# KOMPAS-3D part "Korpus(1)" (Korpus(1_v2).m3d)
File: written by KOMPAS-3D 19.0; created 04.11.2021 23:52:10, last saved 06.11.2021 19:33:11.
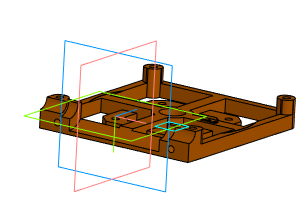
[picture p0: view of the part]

Document properties: Полное имя файла: D:\3D_print\3D проекты Компас 3D\Редуктор (Снова)\Korpus(1_v2).m3d

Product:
- Part/product: Korpus(1)
    Материал: АБС 0603Т ТУ 2214-019-002 03521-96 (density 0 kg/m3)

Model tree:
1. Смещенная плоскость:1  (labels: Подшипник 23 ГОСТ 8338-75\Наружное кольцо; Korpus(1); Операция вращения:1; Операция вращения:1)
     Расстояние = 1.6
2. Эскиз:2  (labels: Подшипник 23 ГОСТ 8338-75\Наружное кольцо; Korpus(1); Скругление:2; Скругление:2)
3. Элемент выдавливания:1  (labels: Korpus(1))
     Расстояние 1 = 11.5
4. Эскиз:3  (labels: Korpus(1))
5. Элемент выдавливания:2
     Расстояние 1 = 34.6; Расстояние 2 = 34.6
6. Эскиз:4  (labels: Korpus(1))
7. Элемент выдавливания:3  (labels: Подшипник 23 ГОСТ 8338-75\Наружное кольцо; Korpus(1); Операция вращения:1; Операция вращения:1)
     Расстояние 1 = 25.2; Смещение 1 = 0.3; Расстояние 2 = 25.2; Смещение 2 = 0.3
8. Эскиз:6  (with: Эскиз:1)  (labels: Korpus(1))
9. Элемент выдавливания:5  (labels: Подшипник 23 ГОСТ 8338-75\Наружное кольцо; Korpus(1); Операция вращения:1; Операция вращения:1)
     Расстояние 2 = 5.9
10. Эскиз:9  (with: Элемент выдавливания:5)
11. Элемент выдавливания:8  (with: Элемент выдавливания:1)
     Расстояние 2 = 4.2; Смещение 2 = 1.4
12. Эскиз:10  (with: Элемент выдавливания:1)  (labels: Гайка М3-6H ГОСТ 5915-70; Korpus(1); Фаска:3; Фаска:3)
13. Элемент выдавливания:9
     Расстояние 2 = 11.5
14. Эскиз:12  (with: Элемент выдавливания:1, Элемент выдавливания:2)  (labels: Гайка М3-6H ГОСТ 5915-70; Korpus(1); Фаска:3; Фаска:3)
15. Элемент выдавливания:10
     Расстояние 2 = 11.5
16. Эскиз:13  (with: Элемент выдавливания:1)  (labels: Korpus(1))
17. Элемент выдавливания:11  (labels: Подшипник 23 ГОСТ 8338-75\Наружное кольцо; Korpus(1); Операция вращения:1; Операция вращения:1)
     Расстояние 1 = 20.9; Расстояние 2 = 20.9
18. Скругление:2  (with: Элемент выдавливания:1)
     Радиус = 4
19. Эскиз:15  (with: Элемент выдавливания:1, Элемент выдавливания:2)
20. Элемент выдавливания:12  (with: Элемент выдавливания:10, Эскиз:16, Элемент выдавливания:5)  (labels: Переходник на Nema_17; Reductor\Korpus(1))
     Расстояние 2 = 7.41561
21. Элемент выдавливания:13  (with: Элемент выдавливания:5)
     Расстояние 2 = 3
22. Эскиз:17  (with: Элемент выдавливания:5)
23. Элемент выдавливания:14
24. Эскиз:18  (with: Элемент выдавливания:1, Элемент выдавливания:10)
25. Элемент выдавливания:15
     Расстояние 2 = 69.2
26. Скругление:3  (with: Элемент выдавливания:15)
     Радиус = 3
27. Эскиз:20  (with: Элемент выдавливания:1, Скругление:5)  (labels: Korpus(2); Korpus(1))
28. Элемент выдавливания:17  (with: Элемент выдавливания:10)
     Расстояние 2 = 3.60261
29. Скругление:5  (with: Элемент выдавливания:17)  (labels: АБС 0603Т ТУ 2214-019-002 03521-96)
     Радиус = 3

Referenced files in D:\3D_print\3D проекты Компас 3D\Редуктор (Снова)\: Намоточный станок (Projects 6).a3d, R-10 - Reductor.a3d
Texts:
  Segoe UI Black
